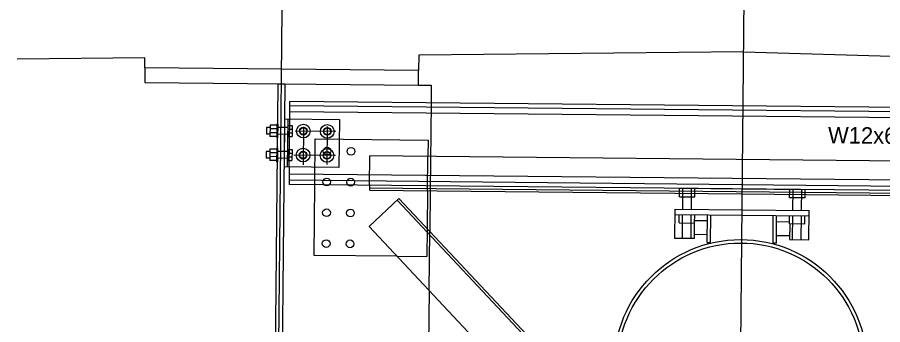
# Model space of a CAD drawing. Extents: x 632312 to 632885, y 378199 to 378534.
# Drawn here: x 632337.55 to 632348.09, y 378392.88 to 378396.62 of the extents above; entities that cross this region are included whole.
import ezdxf

# ---------------------------------------------------------------- set-up
doc = ezdxf.new("R2010")
doc.units = 0
for name, color, linetype in [('B_Boring', 7, 'Continuous'), ('B_Boring Annot', 7, 'Continuous'), ('R_Proposed Const Limits Cut', 7, 'Continuous'), ('R_Road Edge of Shoulder', 7, 'Continuous'), ('R_Shade Removal', 7, 'Continuous'), ('R_Wall', 7, 'Continuous'), ('SHT_Dimensions', 7, 'Continuous')]:
    doc.layers.add(name, color=color, linetype=linetype)

msp = doc.modelspace()

# ---------------------------------------------------------------- linework, layer by layer
at = {"layer": 'B_Boring'}
for p, q in [((632342.431, 378395.791), (632342.587, 378395.789)), ((632342.587, 378395.789), (632342.585, 378395.575)), ((632340.865, 378395.379), (632340.867, 378395.592)), ((632351.907, 378395.432), (632340.866, 378395.541)), ((632351.908, 378395.482), (632340.867, 378395.592)), ((632340.624, 378395.303), (632340.623, 378395.168)), ((632340.707, 378395.303), (632340.624, 378395.303)), ((632340.708, 378395.318), (632340.706, 378395.152)), ((632340.718, 378395.318), (632340.708, 378395.318)), ((632340.718, 378395.318), (632340.716, 378395.152)), ((632340.802, 378395.38), (632341.469, 378395.373)), ((632340.838, 378394.796), (632340.844, 378395.379)), ((632340.843, 378395.301), (632340.842, 378395.166)), ((632340.843, 378395.301), (632340.895, 378395.301)), ((632340.895, 378395.301), (632340.894, 378395.165)), ((632341.469, 378395.373), (632341.463, 378394.79)), ((632340.582, 378395.278), (632340.581, 378395.195)), ((632340.623, 378395.194), (632340.581, 378395.195)), ((632340.624, 378395.277), (632340.582, 378395.278)), ((632340.707, 378395.212), (632340.623, 378395.213)), ((632340.707, 378395.258), (632340.624, 378395.258)), ((632340.842, 378395.256), (632340.895, 378395.256)), ((632340.842, 378395.211), (632340.894, 378395.211)), ((632340.706, 378395.167), (632340.623, 378395.168)), ((632340.716, 378395.152), (632340.706, 378395.152)), ((632340.842, 378395.166), (632340.894, 378395.165)), ((632342.55, 378395.123), (632342.55, 378395.123)), ((632340.579, 378394.986), (632340.579, 378394.903)), ((632340.621, 378394.986), (632340.579, 378394.986)), ((632340.621, 378395.012), (632340.62, 378394.876)), ((632340.705, 378395.011), (632340.621, 378395.012)), ((632340.705, 378395.027), (632340.703, 378394.86)), ((632340.715, 378395.027), (632340.705, 378395.027)), ((632340.715, 378395.027), (632340.714, 378394.86)), ((632340.84, 378395.01), (632340.839, 378394.874)), ((632340.84, 378395.01), (632340.892, 378395.009)), ((632340.892, 378395.009), (632340.891, 378394.874)), ((632340.62, 378394.902), (632340.579, 378394.903)), ((632340.704, 378394.921), (632340.62, 378394.922)), ((632340.703, 378394.876), (632340.62, 378394.876)), ((632340.704, 378394.966), (632340.621, 378394.967)), ((632340.839, 378394.919), (632340.891, 378394.919)), ((632340.839, 378394.874), (632340.891, 378394.874)), ((632340.84, 378394.965), (632340.892, 378394.964)), ((632340.714, 378394.86), (632340.703, 378394.86)), ((632341.463, 378394.79), (632340.796, 378394.797)), ((632340.859, 378394.796), (632340.857, 378394.583)), ((632351.898, 378394.524), (632340.857, 378394.634)), ((632351.898, 378394.474), (632340.857, 378394.583)), ((632341.161, 378393.72), (632341.169, 378394.58)), ((632341.836, 378394.574), (632341.835, 378394.513)), ((632341.835, 378394.513), (632346.377, 378394.468)), ((632342.575, 378394.506), (632342.57, 378394.015)), ((632345.61, 378394.434), (632345.611, 378394.536)), ((632347.143, 378394.519), (632345.611, 378394.534)), ((632345.651, 378394.281), (632345.653, 378394.536)), ((632345.756, 378394.28), (632345.758, 378394.535)), ((632345.799, 378394.432), (632345.8, 378394.534)), ((632346.377, 378394.468), (632350.918, 378394.423)), ((632346.953, 378394.421), (632346.954, 378394.523)), ((632346.994, 378394.268), (632346.996, 378394.522)), ((632347.098, 378394.267), (632347.101, 378394.521)), ((632347.142, 378394.419), (632347.143, 378394.521)), ((632345.61, 378394.434), (632345.799, 378394.432)), ((632347.142, 378394.419), (632346.953, 378394.421)), ((632345.555, 378393.927), (632345.558, 378394.282)), ((632345.558, 378394.282), (632347.191, 378394.266)), ((632347.187, 378393.911), (632347.191, 378394.266)), ((632345.558, 378394.219), (632347.19, 378394.202)), ((632345.607, 378394.116), (632345.608, 378394.218)), ((632345.647, 378393.926), (632345.65, 378394.218)), ((632345.752, 378393.925), (632345.755, 378394.217)), ((632345.796, 378394.114), (632345.797, 378394.216)), ((632345.952, 378394.14), (632345.797, 378394.141)), ((632345.949, 378393.879), (632345.953, 378394.215)), ((632345.99, 378393.879), (632345.994, 378394.214)), ((632346.751, 378393.871), (632346.754, 378394.207)), ((632346.792, 378393.871), (632346.795, 378394.206)), ((632346.795, 378394.131), (632346.95, 378394.13)), ((632346.95, 378394.103), (632346.951, 378394.205)), ((632346.99, 378393.913), (632346.993, 378394.204)), ((632347.095, 378393.912), (632347.098, 378394.203)), ((632347.139, 378394.101), (632347.14, 378394.203)), ((632345.607, 378394.116), (632345.796, 378394.114)), ((632345.791, 378394.114), (632345.789, 378393.925)), ((632347.139, 378394.101), (632346.95, 378394.103)), ((632346.955, 378394.103), (632346.953, 378393.913)), ((632345.789, 378393.925), (632345.555, 378393.927)), ((632345.95, 378393.972), (632345.789, 378393.973)), ((632346.793, 378393.963), (632346.954, 378393.962)), ((632345.949, 378393.879), (632345.99, 378393.879)), ((632346.792, 378393.871), (632346.751, 378393.871)), ((632346.953, 378393.913), (632347.187, 378393.911)), ((632342.171, 378393.71), (632341.161, 378393.72)), ((632342.563, 378393.292), (632342.521, 378389.095))]:
    msp.add_line(p, q, dxfattribs=at)
for points in [[(632342.431, 378395.791), (632342.433, 378395.968), (632339.1, 378396.001), (632339.098, 378395.824)], [(632340.687, 378383.808), (632340.604, 378383.808), (632340.723, 378395.808), (632340.806, 378395.807)]]:
    msp.add_lwpolyline(points, close=True, dxfattribs=at)
for points in [[(632342.543, 378394.506), (632342.539, 378394.048)], [(632344.305, 378391.436), (632341.831, 378394.072), (632342.195, 378394.414), (632344.312, 378392.159)]]:
    msp.add_lwpolyline(points, dxfattribs=at)
for centre, radius in [((632341.03, 378395.232), 0.0469), ((632341.321, 378395.229), 0.0469), ((632341.027, 378394.94), 0.0469), ((632341.319, 378394.989), 0.0469), ((632341.318, 378394.937), 0.0469), ((632341.611, 378394.986), 0.0469), ((632341.315, 378394.614), 0.0469), ((632341.607, 378394.611), 0.0469), ((632341.312, 378394.239), 0.0469), ((632341.603, 378394.236), 0.0469), ((632341.308, 378393.864), 0.0469), ((632341.599, 378393.861), 0.0469), ((632346.356, 378392.371), 1.542), ((632346.356, 378392.371), 1.5)]:
    msp.add_circle(centre, radius, dxfattribs=at)
at = {"layer": 'B_Boring Annot'}
for p, q in [((632342.435, 378396.157), (632342.433, 378395.968)), ((632346.394, 378396.197), (632342.435, 378396.157)), ((632346.394, 378396.197), (632350.351, 378396.079)), ((632339.101, 378396.124), (632337.546, 378396.108)), ((632339.1, 378396.001), (632339.101, 378396.124)), ((632342.433, 378395.968), (632339.1, 378396.001))]:
    msp.add_line(p, q, dxfattribs=at)
at = {"layer": 'R_Proposed Const Limits Cut'}
for p, q in [((632342.585, 378395.575), (632342.575, 378394.506)), ((632351.906, 378395.357), (632340.865, 378395.467)), ((632340.859, 378394.796), (632340.865, 378395.379)), ((632340.842, 378395.192), (632340.717, 378395.193)), ((632340.843, 378395.275), (632340.718, 378395.277)), ((632341.169, 378394.58), (632341.175, 378395.137)), ((632341.175, 378395.137), (632342.55, 378395.123)), ((632342.55, 378395.123), (632342.548, 378394.923)), ((632340.84, 378394.984), (632340.715, 378394.985)), ((632340.839, 378394.9), (632340.714, 378394.902)), ((632341.836, 378394.574), (632341.839, 378394.93)), ((632350.922, 378394.84), (632341.839, 378394.93)), ((632342.543, 378394.506), (632342.548, 378394.923)), ((632351.899, 378394.599), (632340.858, 378394.708)), ((632350.918, 378394.449), (632341.835, 378394.539)), ((632342.173, 378394.393), (632350.804, 378385.197)), ((632342.539, 378394.048), (632342.535, 378393.706)), ((632342.563, 378393.292), (632342.57, 378394.015)), ((632342.171, 378393.71), (632342.535, 378393.706))]:
    msp.add_line(p, q, dxfattribs=at)
for centre, radius in [((632341.03, 378395.232), 0.0833), ((632341.321, 378395.229), 0.0833), ((632341.03, 378395.232), 0.0417), ((632341.321, 378395.229), 0.0417), ((632341.027, 378394.94), 0.0833), ((632341.027, 378394.94), 0.0417), ((632341.318, 378394.937), 0.0833), ((632341.318, 378394.937), 0.0417)]:
    msp.add_circle(centre, radius, dxfattribs=at)
at = {"layer": 'R_Road Edge of Shoulder'}
msp.add_line((632346.226, 378379.285), (632346.556, 378412.526), dxfattribs=at)
at = {"layer": 'R_Shade Removal'}
msp.add_line((632340.634, 378382.631), (632340.773, 378396.703), dxfattribs=at)
at = {"layer": 'R_Wall'}
for p, q in [((632341.426, 378395.228), (632340.931, 378395.233)), ((632341.03, 378395.286), (632341.026, 378394.823)), ((632341.322, 378395.289), (632341.317, 378394.824)), ((632341.423, 378394.936), (632340.913, 378394.941))]:
    msp.add_line(p, q, dxfattribs=at)
at = {"layer": 'SHT_Dimensions'}
msp.add_line((632340.802, 378395.38), (632340.796, 378394.797), dxfattribs=at)
msp.add_circle((632341.03, 378395.232), 0.0469, dxfattribs=at)

# ---------------------------------------------------------------- texts
msp.add_text('W12x65', height=0.2, rotation=359.4304, dxfattribs=at).set_placement((632347.42, 378395.084))

doc.saveas('drawing.dxf')
